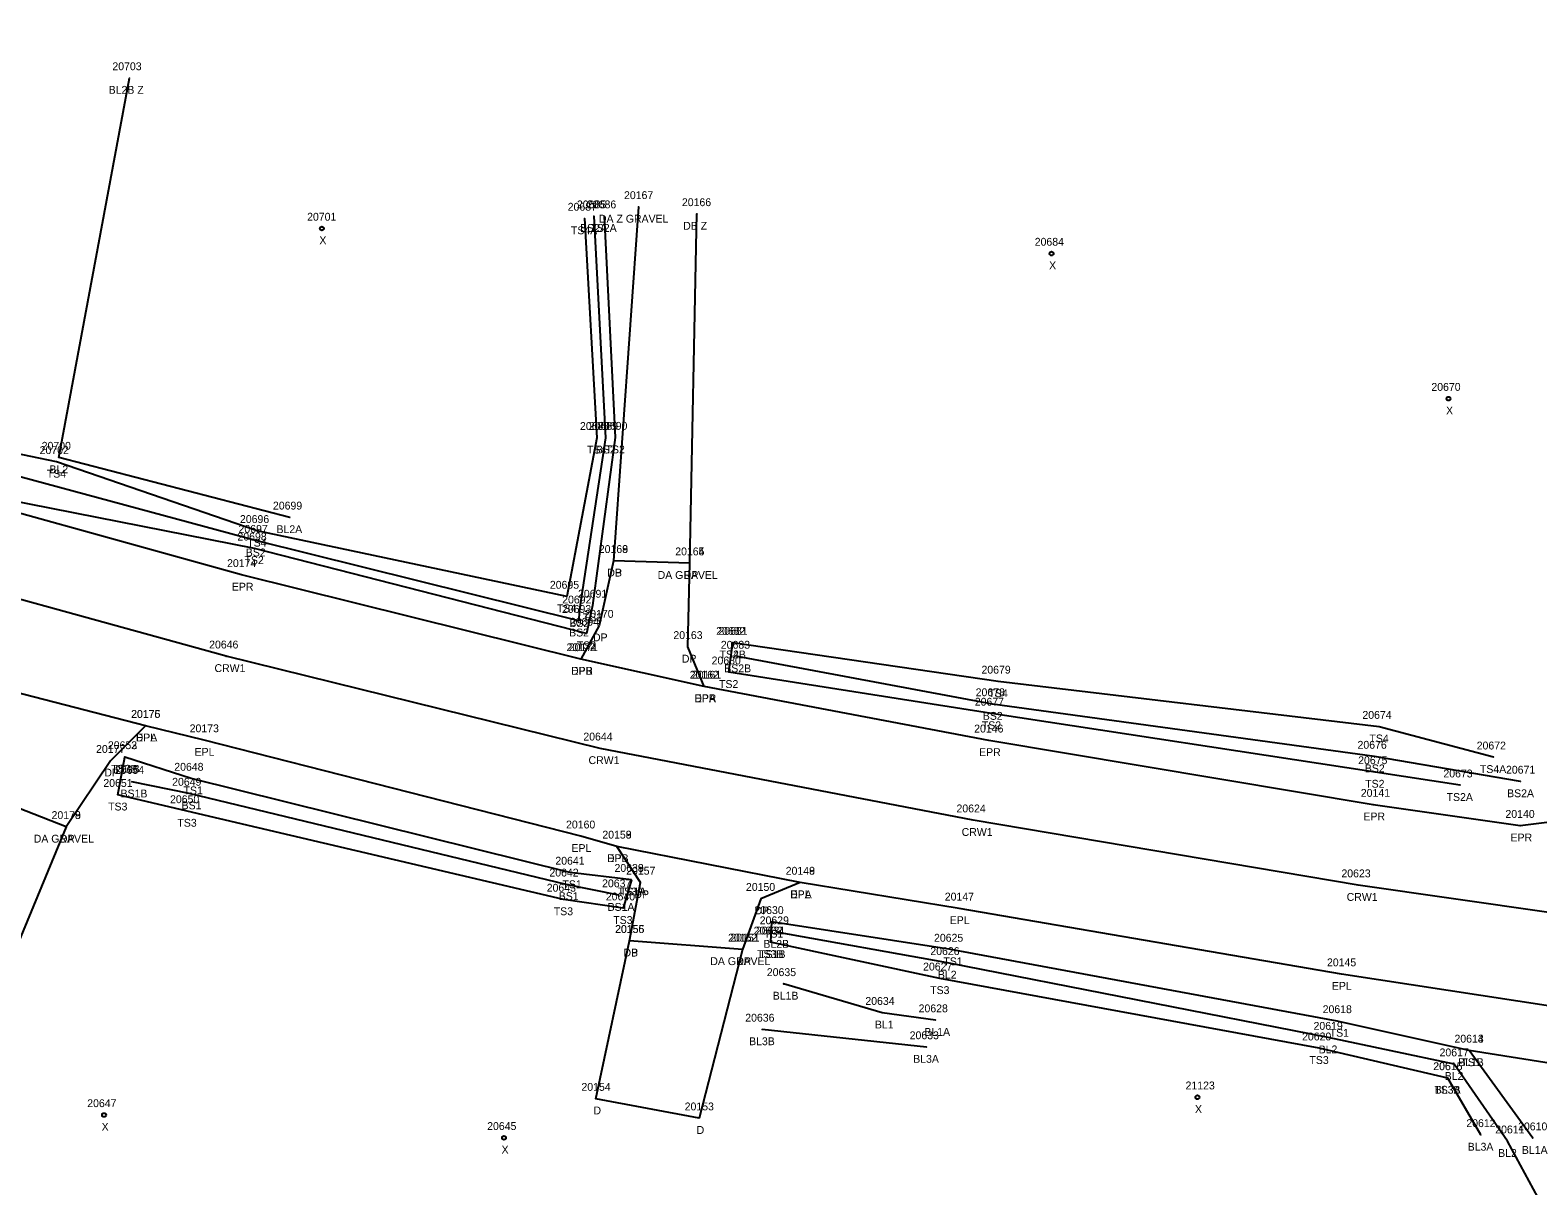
# Model space of a CAD drawing. Extents: x 1813127 to 1818290, y 1178171 to 1179900.
# Drawn here: x 1813328.5 to 1813520.5, y 1178739.3 to 1178886.5 of the extents above; entities that cross this region are included whole.
import ezdxf

# ---------------------------------------------------------------- set-up
doc = ezdxf.new("R2010")
doc.units = 0
for name, color, linetype in [('RD_DTM_BkLn1', 7, 'Continuous'), ('RD_DTM_BkLn2', 7, 'Continuous'), ('RD_EX_Driveway', 7, 'Continuous'), ('RD_EX_Driveway_txCode', 7, 'Continuous'), ('RD_EX_Road', 7, 'Continuous'), ('RD_EX_Road_txCode', 7, 'Continuous'), ('RD_SMD_Locator', 7, 'Continuous'), ('RD_SMD_Misc', 7, 'Continuous')]:
    doc.layers.add(name, color=color, linetype=linetype)

msp = doc.modelspace()

# ---------------------------------------------------------------- linework, layer by layer
at = {"layer": 'RD_DTM_BkLn1'}
for p, q in [((1813442.63, 1178757), (1813421.73, 1178759.24)), ((1813519.83, 1178745.4), (1813511.7, 1178756.57)), ((1813513.21, 1178745.81), (1813509.01, 1178753.06))]:
    msp.add_line(p, q, dxfattribs=at)
for points in [[(1813361.58, 1178824.45), (1813332.19, 1178832.07), (1813341.16, 1178880.4)], [(1813740.76, 1178717.86), (1813693.97, 1178742.65), (1813652.18, 1178753.85), (1813643.74, 1178755.64), (1813595, 1178763.51), (1813546.44, 1178770.61), (1813497.6, 1178777.62), (1813448.59, 1178785.89), (1813401.09, 1178795.04), (1813353.48, 1178806.76), (1813306.05, 1178819.85), (1813260.03, 1178834.12), (1813213.64, 1178849.47), (1813166.61, 1178866.29)], [(1813521.54, 1178735.83), (1813516.61, 1178745.01), (1813509.8, 1178754.82), (1813493.76, 1178758.2), (1813445.29, 1178767.72), (1813423.54, 1178771.64)], [(1813443.77, 1178760.43), (1813436.99, 1178761.37), (1813424.45, 1178765.04)]]:
    msp.add_lwpolyline(points, dxfattribs=at)
at = {"layer": 'RD_DTM_BkLn2'}
for points in [[(1813399.11, 1178862.51), (1813400.66, 1178834.59), (1813396.83, 1178814.37), (1813357.41, 1178822.74), (1813331.9, 1178831.52), (1813325.37, 1178832.88), (1813310.54, 1178837.02), (1813266.49, 1178855.54), (1813220.54, 1178869.08), (1813171.6, 1178886.5)], [(1813400.27, 1178862.81), (1813401.78, 1178834.6), (1813398.4, 1178812.49), (1813398.37, 1178811.29), (1813357.2, 1178821.49), (1813308.85, 1178834.57), (1813264.85, 1178849.55), (1813219.03, 1178864.91), (1813170.13, 1178882.22)], [(1813401.59, 1178862.81), (1813403.02, 1178834.61), (1813400.13, 1178813.23), (1813399.37, 1178809.66), (1813357.07, 1178820.51), (1813311.17, 1178829.54), (1813264.4, 1178847.94), (1813218.33, 1178862.86), (1813169.73, 1178880.34)], [(1813510.57, 1178790.34), (1813499.73, 1178792.03), (1813450.92, 1178799.48), (1813417.46, 1178804.73), (1813418, 1178808.5)], [(1813514.81, 1178793.9), (1813500.27, 1178797.8), (1813451.77, 1178803.56), (1813418, 1178808.5)], [(1813518.26, 1178790.82), (1813499.66, 1178793.99), (1813451.03, 1178800.68), (1813418.59, 1178806.73)], [(1813405.06, 1178778.31), (1813404, 1178774.68), (1813396.43, 1178775.79), (1813348.52, 1178787.06), (1813339.71, 1178789.13), (1813340.57, 1178793.94)], [(1813405.06, 1178778.31), (1813397.25, 1178779.23), (1813349.02, 1178791.19), (1813340.57, 1178793.94)], [(1813403.48, 1178776.35), (1813396.77, 1178777.72), (1813348.76, 1178789.28), (1813341.46, 1178790.79)], [(1813728.98, 1178703.48), (1813680.74, 1178720.54), (1813670.9, 1178725.8), (1813665.35, 1178733.78), (1813654.36, 1178734.63), (1813647.32, 1178729.73), (1813639.1, 1178730.74), (1813591.11, 1178743.16), (1813543.28, 1178751.57), (1813511.7, 1178756.57), (1813494.92, 1178760.32), (1813445.74, 1178769.42), (1813422.91, 1178772.94), (1813422.78, 1178770.34)], [(1813509.01, 1178753.06), (1813492.62, 1178756.85), (1813444.34, 1178765.75), (1813422.78, 1178770.34)]]:
    msp.add_lwpolyline(points, dxfattribs=at)
at = {"layer": 'RD_EX_Driveway'}
for p, q in [((1813405.99, 1178863.99), (1813402.78, 1178818.92)), ((1813412.51, 1178818.62), (1813413.38, 1178863.09))]:
    msp.add_line(p, q, dxfattribs=at)
for points in [[(1813414.35, 1178802.92), (1813412.27, 1178807.96), (1813412.51, 1178818.62), (1813402.78, 1178818.92), (1813400.96, 1178810.67), (1813398.64, 1178806.42)], [(1813343.23, 1178797.92), (1813338.76, 1178793.46), (1813333.1, 1178785.04), (1813321.9, 1178789.4), (1813322.9, 1178794.86), (1813322.95, 1178797.03), (1813321.57, 1178801.49), (1813318.7, 1178804.23)], [(1813333.1, 1178785.04), (1813323.15, 1178761.04), (1813306.52, 1178767.93), (1813321.9, 1178789.4)], [(1813426.54, 1178777.95), (1813421.53, 1178775.89), (1813419.21, 1178769.44), (1813404.84, 1178770.53), (1813406.23, 1178777.96), (1813403.21, 1178782.55)], [(1813419.21, 1178769.44), (1813413.68, 1178747.94), (1813400.54, 1178750.43), (1813404.84, 1178770.53)]]:
    msp.add_lwpolyline(points, dxfattribs=at)
at = {"layer": 'RD_EX_Road'}
for points in [[(1813522.62, 1178785.74), (1813518.21, 1178785.19), (1813499.47, 1178787.87), (1813450.56, 1178796.06), (1813414.35, 1178802.92), (1813398.64, 1178806.42), (1813355.44, 1178817.13), (1813309.85, 1178829.79), (1813263.76, 1178844.1), (1813216.84, 1178859.81), (1813169.03, 1178877.13)], [(1813732.94, 1178707.95), (1813689.88, 1178731.75), (1813641.71, 1178744.36), (1813593.37, 1178752.09), (1813544.49, 1178758.77), (1813495.45, 1178766.29), (1813446.8, 1178774.66), (1813426.54, 1178777.95), (1813403.21, 1178782.55), (1813398.65, 1178783.84), (1813350.68, 1178796.09), (1813343.23, 1178797.92), (1813318.7, 1178804.23), (1813303.26, 1178808.85), (1813256.8, 1178823.17), (1813209.81, 1178838.91), (1813163.27, 1178855.57)]]:
    msp.add_lwpolyline(points, dxfattribs=at)
at = {"layer": 'RD_SMD_Locator'}
for centre, radius in [((1813341.16, 1178880.4), 0.001), ((1813399.11, 1178862.51), 0.001), ((1813400.27, 1178862.81), 0.001), ((1813401.59, 1178862.81), 0.001), ((1813405.99, 1178863.99), 0.001), ((1813413.38, 1178863.09), 0.001), ((1813365.67, 1178861.24), 0.25), ((1813458.55, 1178858.05), 0.25), ((1813509.08, 1178839.57), 0.25), ((1813400.66, 1178834.59), 0.001), ((1813401.78, 1178834.6), 0.001), ((1813403.02, 1178834.61), 0.001), ((1813332.19, 1178832.07), 0.001), ((1813331.9, 1178831.52), 0.001), ((1813361.58, 1178824.45), 0.001), ((1813357.41, 1178822.74), 0.001), ((1813357.07, 1178820.51), 0.001), ((1813357.2, 1178821.49), 0.001), ((1813402.78, 1178818.92), 0.001), ((1813402.78, 1178818.92), 0.001), ((1813412.51, 1178818.62), 0.001), ((1813412.51, 1178818.62), 0.001), ((1813355.44, 1178817.13), 0.001), ((1813396.83, 1178814.37), 0.001), ((1813400.13, 1178813.23), 0.001), ((1813398.37, 1178811.29), 0.001), ((1813398.4, 1178812.49), 0.001), ((1813400.96, 1178810.67), 0.001), ((1813399.37, 1178809.66), 0.001), ((1813412.27, 1178807.96), 0.001), ((1813418, 1178808.5), 0.001), ((1813418, 1178808.5), 0.001), ((1813353.48, 1178806.76), 0.001), ((1813398.64, 1178806.42), 0.001), ((1813398.64, 1178806.42), 0.001), ((1813418.59, 1178806.73), 0.001), ((1813417.46, 1178804.73), 0.001), ((1813451.77, 1178803.56), 0.001), ((1813414.35, 1178802.92), 0.001), ((1813414.35, 1178802.92), 0.001), ((1813450.92, 1178799.48), 0.001), ((1813451.03, 1178800.68), 0.001), ((1813343.23, 1178797.92), 0.001), ((1813343.23, 1178797.92), 0.001), ((1813500.27, 1178797.8), 0.001), ((1813350.68, 1178796.09), 0.001), ((1813450.56, 1178796.06), 0.001), ((1813338.76, 1178793.46), 0.001), ((1813340.57, 1178793.94), 0.001), ((1813340.57, 1178793.94), 0.001), ((1813401.09, 1178795.04), 0.001), ((1813499.66, 1178793.99), 0.001), ((1813514.81, 1178793.9), 0.001), ((1813499.73, 1178792.03), 0.001), ((1813341.46, 1178790.79), 0.001), ((1813349.02, 1178791.19), 0.001), ((1813510.57, 1178790.34), 0.001), ((1813518.26, 1178790.82), 0.001), ((1813339.71, 1178789.13), 0.001), ((1813348.76, 1178789.28), 0.001), ((1813499.47, 1178787.87), 0.001), ((1813348.52, 1178787.06), 0.001), ((1813448.59, 1178785.89), 0.001), ((1813333.1, 1178785.04), 0.001), ((1813333.1, 1178785.04), 0.001), ((1813398.65, 1178783.84), 0.001), ((1813518.21, 1178785.19), 0.001), ((1813403.21, 1178782.55), 0.001), ((1813403.21, 1178782.55), 0.001), ((1813397.25, 1178779.23), 0.001), ((1813405.06, 1178778.31), 0.001), ((1813405.06, 1178778.31), 0.001), ((1813396.77, 1178777.72), 0.001), ((1813403.48, 1178776.35), 0.001), ((1813406.23, 1178777.96), 0.001), ((1813426.54, 1178777.95), 0.001), ((1813426.54, 1178777.95), 0.001), ((1813497.6, 1178777.62), 0.001), ((1813396.43, 1178775.79), 0.001), ((1813404, 1178774.68), 0.001), ((1813421.53, 1178775.89), 0.001), ((1813446.8, 1178774.66), 0.001), ((1813422.91, 1178772.94), 0.001), ((1813404.84, 1178770.53), 0.001), ((1813404.84, 1178770.53), 0.001), ((1813422.78, 1178770.34), 0.001), ((1813422.78, 1178770.34), 0.001), ((1813423.54, 1178771.64), 0.001), ((1813419.21, 1178769.44), 0.001), ((1813419.21, 1178769.44), 0.001), ((1813445.74, 1178769.42), 0.001), ((1813445.29, 1178767.72), 0.001), ((1813424.45, 1178765.04), 0.001), ((1813444.34, 1178765.75), 0.001), ((1813495.45, 1178766.29), 0.001), ((1813436.99, 1178761.37), 0.001), ((1813421.73, 1178759.24), 0.001), ((1813443.77, 1178760.43), 0.001), ((1813494.92, 1178760.32), 0.001), ((1813442.63, 1178757), 0.001), ((1813493.76, 1178758.2), 0.001), ((1813492.62, 1178756.85), 0.001), ((1813511.7, 1178756.57), 0.001), ((1813511.7, 1178756.57), 0.001), ((1813509.8, 1178754.82), 0.001), ((1813509.01, 1178753.06), 0.001), ((1813509.01, 1178753.06), 0.001), ((1813400.54, 1178750.43), 0.001), ((1813477.12, 1178750.61), 0.25), ((1813337.94, 1178748.35), 0.25), ((1813413.68, 1178747.94), 0.001), ((1813388.85, 1178745.44), 0.25), ((1813513.21, 1178745.81), 0.001), ((1813519.83, 1178745.4), 0.001), ((1813516.61, 1178745.01), 0.001)]:
    msp.add_circle(centre, radius, dxfattribs=at)

# ---------------------------------------------------------------- texts
at = {"layer": 'RD_EX_Driveway_txCode'}
for s, p in [('20167', (1813404.13, 1178864.99)), ('20166', (1813411.5, 1178864.09)), ('DA Z GRAVEL', (1813400.94, 1178861.99)), ('DB Z', (1813411.66, 1178861.09)), ('20168', (1813400.92, 1178819.92)), ('20169', (1813400.92, 1178819.92)), ('20164', (1813410.65, 1178819.62)), ('20165', (1813410.65, 1178819.62)), ('DB', (1813402, 1178816.92)), ('DP', (1813402, 1178816.92)), ('DA GRAVEL', (1813408.41, 1178816.62)), ('DP', (1813411.73, 1178816.62)), ('20170', (1813399.08, 1178811.67)), ('DP', (1813400.18, 1178808.67)), ('20163', (1813410.41, 1178808.96)), ('20171', (1813397.09, 1178807.42)), ('DP', (1813411.49, 1178805.96)), ('DPB', (1813397.39, 1178804.42)), ('20162', (1813412.49, 1178803.92)), ('DPA', (1813413.08, 1178800.92)), ('20176', (1813341.38, 1178798.92)), ('20177', (1813336.92, 1178794.46)), ('DPA', (1813341.97, 1178795.92)), ('DP', (1813337.98, 1178791.46)), ('20178', (1813331.26, 1178786.04)), ('20179', (1813331.26, 1178786.04)), ('DA GRAVEL', (1813328.99, 1178783.04)), ('DP', (1813332.32, 1178783.04)), ('20158', (1813401.37, 1178783.55)), ('DPB', (1813401.96, 1178780.55)), ('20157', (1813404.4, 1178778.96)), ('20149', (1813424.71, 1178778.95)), ('DP', (1813405.45, 1178775.96)), ('20150', (1813419.65, 1178776.89)), ('DPA', (1813425.27, 1178775.95)), ('DP', (1813420.75, 1178773.89)), ('20156', (1813402.98, 1178771.53)), ('20155', (1813403.01, 1178771.53)), ('20152', (1813417.38, 1178770.44)), ('20151', (1813417.66, 1178770.44)), ('DB', (1813404.06, 1178768.53)), ('DP', (1813404.06, 1178768.53)), ('DA GRAVEL', (1813415.11, 1178767.44)), ('DP', (1813418.43, 1178767.44)), ('20154', (1813398.71, 1178751.43)), ('D', (1813400.24, 1178748.43)), ('20153', (1813411.85, 1178748.94)), ('D', (1813413.37, 1178745.94))]:
    msp.add_text(s, height=1, dxfattribs=at).set_placement(p)
at = {"layer": 'RD_EX_Road_txCode'}
for s, p in [('20174', (1813353.6, 1178818.13)), ('EPR', (1813354.21, 1178815.13)), ('20172', (1813396.81, 1178807.42)), ('EPR', (1813397.42, 1178804.42)), ('20161', (1813412.77, 1178803.92)), ('EPR', (1813413.12, 1178800.92)), ('20175', (1813341.4, 1178798.92)), ('20173', (1813348.84, 1178797.09)), ('20146', (1813448.7, 1178797.06)), ('EPL', (1813342.03, 1178795.92)), ('EPL', (1813349.47, 1178794.09)), ('EPR', (1813449.33, 1178794.06)), ('20141', (1813497.92, 1178788.87)), ('20160', (1813396.75, 1178784.84)), ('EPR', (1813498.25, 1178785.87)), ('20140', (1813516.33, 1178786.19)), ('20159', (1813401.37, 1178783.55)), ('EPR', (1813516.98, 1178783.19)), ('EPL', (1813397.44, 1178781.84)), ('EPL', (1813402, 1178780.55)), ('20148', (1813424.71, 1178778.95)), ('EPL', (1813425.34, 1178775.95)), ('20147', (1813444.96, 1178775.66)), ('EPL', (1813445.59, 1178772.66)), ('20145', (1813493.61, 1178767.29)), ('EPL', (1813494.24, 1178764.29))]:
    msp.add_text(s, height=1, dxfattribs=at).set_placement(p)
at = {"layer": 'RD_SMD_Misc'}
for s, p in [('20703', (1813339, 1178881.4)), ('BL2B Z', (1813338.53, 1178878.4)), ('20687', (1813396.96, 1178863.51)), ('20685', (1813398.13, 1178863.81)), ('20686', (1813399.42, 1178863.81)), ('20701', (1813363.79, 1178862.24)), ('TS4A', (1813397.37, 1178860.51)), ('BS2A', (1813398.55, 1178860.81)), ('TS2A', (1813399.85, 1178860.81)), ('X', (1813365.35, 1178859.24)), ('20684', (1813456.41, 1178859.05)), ('X', (1813458.24, 1178856.05)), ('20670', (1813506.9, 1178840.57)), ('X', (1813508.77, 1178837.57)), ('20688', (1813398.52, 1178835.59)), ('20689', (1813399.64, 1178835.6)), ('20690', (1813400.84, 1178835.61)), ('20700', (1813330, 1178833.07)), ('20702', (1813329.74, 1178832.52)), ('TS4', (1813399.42, 1178832.59)), ('BS2', (1813400.55, 1178832.6)), ('TS2', (1813401.78, 1178832.61)), ('TS4', (1813330.65, 1178829.52)), ('BL2', (1813330.99, 1178830.07)), ('20699', (1813359.44, 1178825.45)), ('20696', (1813355.24, 1178823.74)), ('20698', (1813354.92, 1178821.51)), ('20697', (1813355.06, 1178822.49)), ('BL2A', (1813359.89, 1178822.45)), ('BS2', (1813355.98, 1178819.49)), ('TS4', (1813356.17, 1178820.74)), ('TS2', (1813355.82, 1178818.51)), ('20695', (1813394.69, 1178815.37)), ('20692', (1813396.26, 1178813.49)), ('20691', (1813398.27, 1178814.23)), ('TS4', (1813395.59, 1178812.37)), ('20693', (1813396.23, 1178812.29)), ('BS2', (1813397.17, 1178810.49)), ('20694', (1813397.23, 1178810.66)), ('TS2', (1813398.89, 1178811.23)), ('20646', (1813351.32, 1178807.76)), ('BS2', (1813397.14, 1178809.29)), ('20682', (1813415.86, 1178809.5)), ('20681', (1813416.15, 1178809.5)), ('20683', (1813416.45, 1178807.73)), ('TS2', (1813398.12, 1178807.66)), ('TS2B', (1813416.29, 1178806.5)), ('TS4B', (1813416.29, 1178806.5)), ('CRW1', (1813352, 1178804.76)), ('20680', (1813415.28, 1178805.73)), ('BS2B', (1813416.89, 1178804.73)), ('20679', (1813449.63, 1178804.56)), ('TS2', (1813416.22, 1178802.73)), ('20677', (1813448.78, 1178800.48)), ('20678', (1813448.89, 1178801.68)), ('TS4', (1813450.53, 1178801.56)), ('BS2', (1813449.8, 1178798.68)), ('20674', (1813498.12, 1178798.8)), ('TS2', (1813449.68, 1178797.48)), ('20652', (1813338.43, 1178794.94)), ('20653', (1813338.43, 1178794.94)), ('20644', (1813398.95, 1178796.04)), ('20676', (1813497.5, 1178794.99)), ('TS4', (1813499.02, 1178795.8)), ('20672', (1813512.67, 1178794.9)), ('CRW1', (1813399.61, 1178793.04)), ('20675', (1813497.58, 1178793.03)), ('TS3B', (1813338.85, 1178791.94)), ('TS1B', (1813339.14, 1178791.94)), ('20654', (1813339.32, 1178791.79)), ('20648', (1813346.88, 1178792.19)), ('BS2', (1813498.43, 1178791.99)), ('20673', (1813508.43, 1178791.34)), ('TS4A', (1813513.08, 1178791.9)), ('20671', (1813516.4, 1178791.82)), ('20651', (1813337.85, 1178790.13)), ('BS1B', (1813340.04, 1178788.79)), ('20649', (1813346.61, 1178790.28)), ('TS1', (1813348.06, 1178789.19)), ('TS2', (1813498.48, 1178790.03)), ('BS2A', (1813516.54, 1178788.82)), ('TS3', (1813338.46, 1178787.13)), ('20650', (1813346.34, 1178788.06)), ('BS1', (1813347.81, 1178787.28)), ('20624', (1813446.45, 1178786.89)), ('TS2A', (1813508.84, 1178788.34)), ('TS3', (1813347.28, 1178785.06)), ('CRW1', (1813447.11, 1178783.89)), ('20641', (1813395.39, 1178780.23)), ('20638', (1813402.92, 1178779.31)), ('20639', (1813402.92, 1178779.31)), ('20642', (1813394.63, 1178778.72)), ('TS1', (1813396.29, 1178777.23)), ('20637', (1813401.34, 1178777.35)), ('20623', (1813495.45, 1178778.62)), ('20643', (1813394.29, 1178776.79)), ('BS1', (1813395.82, 1178775.72)), ('20640', (1813401.82, 1178775.68)), ('TS3A', (1813403.33, 1178776.31)), ('TS1A', (1813403.61, 1178776.31)), ('CRW1', (1813496.12, 1178775.62)), ('TS3', (1813395.19, 1178773.79)), ('BS1A', (1813402.04, 1178774.35)), ('20630', (1813420.73, 1178773.94)), ('TS3', (1813402.76, 1178772.68)), ('20632', (1813420.63, 1178771.34)), ('20631', (1813420.92, 1178771.34)), ('20629', (1813421.4, 1178772.64)), ('BL2B', (1813421.87, 1178769.64)), ('TS1', (1813421.95, 1178770.94)), ('20625', (1813443.59, 1178770.42)), ('TS3B', (1813421.06, 1178768.34)), ('TS1B', (1813421.34, 1178768.34)), ('20626', (1813443.12, 1178768.72)), ('TS1', (1813444.78, 1178767.42)), ('20635', (1813422.31, 1178766.04)), ('20627', (1813442.2, 1178766.75)), ('BL2', (1813444.08, 1178765.72)), ('TS3', (1813443.1, 1178763.75)), ('BL1B', (1813423.06, 1178763.04)), ('20634', (1813434.85, 1178762.37)), ('20636', (1813419.56, 1178760.24)), ('20628', (1813441.63, 1178761.43)), ('20618', (1813493.06, 1178761.32)), ('BL1', (1813436.07, 1178759.37)), ('20633', (1813440.49, 1178758)), ('BL1A', (1813442.36, 1178758.43)), ('20620', (1813490.44, 1178757.85)), ('20619', (1813491.9, 1178759.2)), ('TS1', (1813493.96, 1178758.32)), ('BL3B', (1813420.05, 1178757.24)), ('BL2', (1813492.55, 1178756.2)), ('20613', (1813509.84, 1178757.57)), ('20614', (1813509.84, 1178757.57)), ('BL3A', (1813440.94, 1178755)), ('TS3', (1813491.38, 1178754.85)), ('20616', (1813507.13, 1178754.06)), ('20615', (1813507.15, 1178754.06)), ('20617', (1813507.94, 1178755.82)), ('BL1B', (1813510.3, 1178754.57)), ('TS1', (1813510.73, 1178754.57)), ('BL2', (1813508.6, 1178752.82)), ('21123', (1813475.61, 1178751.61)), ('TS3A', (1813507.28, 1178751.06)), ('BL3B', (1813507.33, 1178751.06)), ('20647', (1813335.8, 1178749.35)), ('X', (1813476.81, 1178748.61)), ('X', (1813337.63, 1178746.35)), ('20645', (1813386.71, 1178746.44)), ('20612', (1813511.35, 1178746.81)), ('20610', (1813517.94, 1178746.4)), ('20611', (1813515.03, 1178746.01)), ('X', (1813388.54, 1178743.44)), ('BL3A', (1813511.52, 1178743.81)), ('BL2', (1813515.4, 1178743.01)), ('BL1A', (1813518.42, 1178743.4))]:
    msp.add_text(s, height=1, dxfattribs=at).set_placement(p)

doc.saveas('drawing.dxf')
